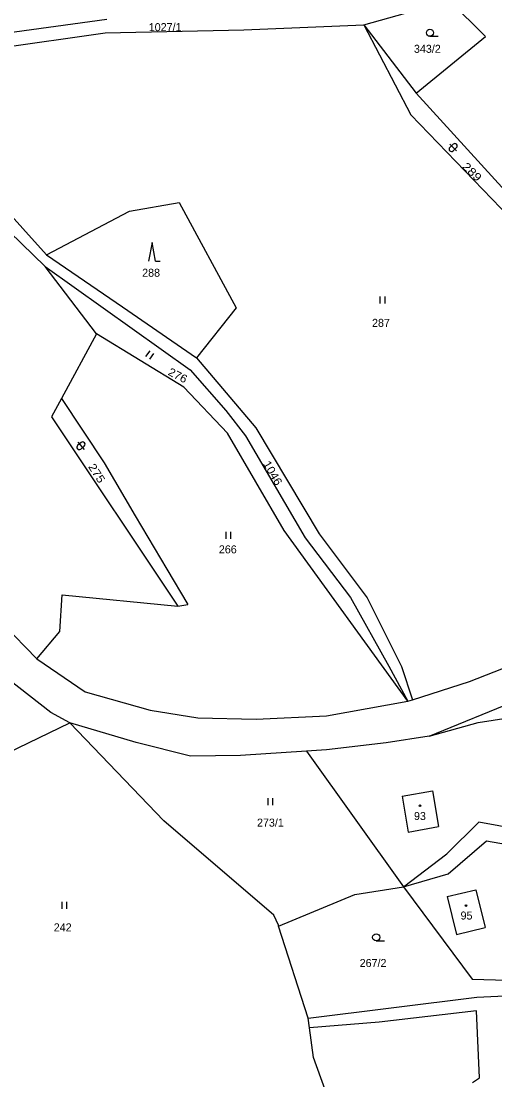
# Model space of a CAD drawing. Extents: x -744132 to -742433, y -984679 to -982287.
# Drawn here: x -743040.9 to -742940.3, y -984060.3 to -983835.5 of the extents above; entities that cross this region are included whole.
import ezdxf

# ---------------------------------------------------------------- set-up
doc = ezdxf.new("R2010")
doc.units = 0
doc.header["$LTSCALE"] = 0.68
for name, color, linetype, lineweight in [('1', 7, 'Continuous', 25), ('3', 7, 'Continuous', 25), ('5', 7, 'Continuous', 25)]:
    doc.layers.add(name, color=color, linetype=linetype, lineweight=lineweight)
doc.layers.add('2', color=7, linetype='Continuous')

msp = doc.modelspace()

# ---------------------------------------------------------------- linework, layer by layer
at = {"layer": '1'}
for p, q in [((-742968.16, -983836.35), (-742949.95, -983831.25)), ((-742949.95, -983831.25), (-742942.3, -983838.82)), ((-743022.73, -983835.22), (-743059.72, -983840.28)), ((-742993.61, -983837.37), (-742968.16, -983836.35)), ((-742968.16, -983836.35), (-742958.15, -983855.44)), ((-742968.16, -983836.35), (-742957.02, -983850.8)), ((-743061.62, -983843.55), (-743023.06, -983837.99)), ((-743023.06, -983837.99), (-742993.61, -983837.37)), ((-742957.02, -983850.8), (-742942.3, -983838.82)), ((-742957.02, -983850.8), (-742924.88, -983886.12)), ((-742958.15, -983855.44), (-742926.77, -983887.99)), ((-743045.62, -983873.99), (-743035.53, -983885.15)), ((-743017.93, -983875.92), (-743007.35, -983874.07)), ((-743007.35, -983874.07), (-742995.27, -983896.44)), ((-743047.81, -983876.13), (-743035.84, -983887.63)), ((-743035.53, -983885.15), (-743017.93, -983875.92)), ((-743035.53, -983885.15), (-743019.4, -983896.21)), ((-743035.84, -983887.63), (-743005.05, -983909.59)), ((-743024.89, -983901.91), (-743035.84, -983887.63)), ((-743019.4, -983896.21), (-743003.64, -983907.05)), ((-742995.27, -983896.44), (-743003.64, -983907.05)), ((-743024.89, -983901.91), (-743032.36, -983915.64)), ((-743006.34, -983913.24), (-743024.89, -983901.91)), ((-743003.64, -983907.05), (-742991.07, -983921.86)), ((-743005.05, -983909.59), (-742997.41, -983918.19)), ((-742997.12, -983923.03), (-743006.34, -983913.24)), ((-743032.36, -983915.64), (-743034.48, -983919.54)), ((-743032.36, -983915.64), (-743023.26, -983929.35)), ((-743034.48, -983919.54), (-743007.6, -983959.76)), ((-742997.41, -983918.19), (-742993.24, -983923.58)), ((-742991.07, -983921.86), (-742977.63, -983944.4)), ((-742985.08, -983943.71), (-742997.12, -983923.03)), ((-742993.24, -983923.58), (-742980.58, -983945.27)), ((-743023.26, -983929.35), (-743016.66, -983940.61)), ((-743016.66, -983940.61), (-743009.98, -983951.88)), ((-742958.81, -983979.95), (-742985.08, -983943.71)), ((-742980.58, -983945.27), (-742971, -983957.88)), ((-742977.63, -983944.4), (-742967.41, -983957.98)), ((-743009.98, -983951.88), (-743005.49, -983959.37)), ((-743032.69, -983965.11), (-743032.18, -983957.38)), ((-743032.18, -983957.38), (-743007.6, -983959.76)), ((-743007.6, -983959.76), (-743005.49, -983959.37)), ((-742971, -983957.88), (-742962.82, -983972.53)), ((-742967.41, -983957.98), (-742960.14, -983972.54)), ((-743044.73, -983963.56), (-743037.58, -983970.94)), ((-743037.58, -983970.94), (-743032.69, -983965.11)), ((-742945.7, -983975.78), (-742917.94, -983964.86)), ((-743037.58, -983970.94), (-743027.33, -983977.93)), ((-743034.59, -983982.35), (-743046.24, -983973.26)), ((-742962.82, -983972.53), (-742958.81, -983979.95)), ((-742960.14, -983972.54), (-742957.82, -983979.63)), ((-742957.82, -983979.63), (-742945.7, -983975.78)), ((-743027.33, -983977.93), (-743013.5, -983981.81)), ((-742954.25, -983987.39), (-742931.01, -983977.85)), ((-742976.07, -983983.01), (-742958.81, -983979.95)), ((-742958.81, -983979.95), (-742957.82, -983979.63)), ((-743030.59, -983984.53), (-743034.59, -983982.35)), ((-743013.5, -983981.81), (-743003.4, -983983.46)), ((-742943.85, -983984.44), (-742931.13, -983982.52)), ((-743053.26, -983995.45), (-743030.59, -983984.53)), ((-743010.64, -984005.31), (-743030.59, -983984.53)), ((-743003.4, -983983.46), (-742990.97, -983983.76)), ((-742990.97, -983983.76), (-742976.07, -983983.01)), ((-742954.25, -983987.39), (-742943.85, -983984.44)), ((-742994.34, -983991.43), (-743004.94, -983991.6)), ((-742980.31, -983990.54), (-742994.34, -983991.43)), ((-742976.04, -983990.27), (-742980.31, -983990.54)), ((-742980.31, -983990.54), (-742959.7, -984019.36)), ((-742959.98, -984000.08), (-742953.56, -983998.93)), ((-742959.98, -984000.08), (-742958.73, -984007.72)), ((-742953.56, -983998.93), (-742952.31, -984006.57)), ((-742987.25, -984025.33), (-743010.64, -984005.31)), ((-742958.73, -984007.72), (-742952.31, -984006.57)), ((-742950.5, -984012.36), (-742943.7, -984005.59)), ((-742922.34, -984009.55), (-742943.7, -984005.59)), ((-742950.23, -984016.58), (-742942.1, -984009.55)), ((-742942.1, -984009.55), (-742925.39, -984012.53)), ((-742959.7, -984019.36), (-742950.5, -984012.36)), ((-742959.7, -984019.36), (-742950.23, -984016.58)), ((-742970.06, -984020.95), (-742959.7, -984019.36)), ((-742959.7, -984019.36), (-742945.1, -984038.93)), ((-742950.46, -984021.4), (-742944.34, -984019.96)), ((-742944.34, -984019.96), (-742942.33, -984028)), ((-742986.22, -984027.72), (-742970.06, -984020.95)), ((-742950.46, -984021.4), (-742948.45, -984029.44)), ((-742986.28, -984027.52), (-742987.25, -984025.33)), ((-742986.22, -984027.72), (-742986.28, -984027.52)), ((-742979.99, -984047.22), (-742986.22, -984027.72)), ((-742948.45, -984029.44), (-742942.33, -984028)), ((-742945.1, -984038.93), (-742930.55, -984039.41)), ((-742979.99, -984047.22), (-742944.15, -984042.77)), ((-742944.15, -984042.77), (-742930.74, -984042.18)), ((-742979.7, -984049.29), (-742979.99, -984047.22)), ((-742944.22, -984045.71), (-742964.9, -984048.1)), ((-742964.9, -984048.1), (-742979.7, -984049.29)), ((-742978.8, -984055.59), (-742979.7, -984049.29)), ((-742976.37, -984062.42), (-742978.8, -984055.59))]:
    msp.add_line(p, q, dxfattribs=at)
for points in [[(-743004.94, -983991.6), (-743016.49, -983988.73), (-743030.59, -983984.53)], [(-742954.25, -983987.39), (-742963.39, -983988.8), (-742976.04, -983990.27)], [(-742945.05, -984060.92), (-742943.58, -984059.88), (-742944.22, -984045.71)]]:
    msp.add_lwpolyline(points, dxfattribs=at)
at = {"layer": '3'}
for p, q in [((-742954.093, -983838.76), (-742952.343, -983838.76)), ((-742949.149, -983861.668), (-742949.869, -983862.364)), ((-742949.857, -983861.656), (-742948.466, -983863.096)), ((-742949.174, -983863.084), (-742948.454, -983862.388)), ((-743012.37, -983886.52), (-743011.374, -983886.52)), ((-742964.631, -983895.48), (-742964.631, -983893.98)), ((-742963.63, -983895.48), (-742963.63, -983893.98)), ((-743014.423, -983906.74), (-743013.542, -983905.526)), ((-743013.613, -983907.328), (-743012.732, -983906.115)), ((-743028.143, -983924.993), (-743028.91, -983925.636)), ((-743028.848, -983924.931), (-743027.561, -983926.465)), ((-743028.267, -983926.403), (-743027.5, -983925.76)), ((-742997.391, -983945.49), (-742997.391, -983943.99)), ((-742996.39, -983945.49), (-742996.39, -983943.99)), ((-742988.451, -984002.02), (-742988.451, -984000.52)), ((-742987.45, -984002.02), (-742987.45, -984000.52)), ((-743032.211, -984024.01), (-743032.211, -984022.51)), ((-743031.21, -984024.01), (-743031.21, -984022.51)), ((-742965.513, -984030.82), (-742963.763, -984030.82))]:
    msp.add_line(p, q, dxfattribs=at)
msp.add_lwpolyline([(-743012.37, -983886.52), (-743013.12, -983882.52), (-743013.87, -983886.52)], dxfattribs=at)
for centre in [(-742954.0929, -983838.0098), (-742965.5129, -984030.0698)]:
    msp.add_circle(centre, 0.75, dxfattribs=at)
for centre, start, end in [((-742949.521, -983862.7233), 134, 313.98788), ((-742948.8016, -983862.0286), 314, 134), ((-743028.5877, -983926.0192), 130, 309.98789), ((-743027.8216, -983925.3764), 310, 130)]:
    msp.add_arc(centre, 0.5, start, end, dxfattribs=at)
at = {"layer": '5'}
for centre in [(-742956.2168, -984002.1392), (-742946.4468, -984023.3192)]:
    msp.add_circle(centre, 0.175, dxfattribs=at)

# ---------------------------------------------------------------- texts
at = {"layer": '2'}
for s, p in [('1027/1', (-743013.81, -983837.665)), ('343/2', (-742957.49, -983842.265)), ('288', (-743015.21, -983889.815)), ('287', (-742966.39, -983900.455)), ('266', (-742998.92, -983948.545)), ('273/1', (-742990.82, -984006.565)), ('93', (-742957.48, -984005.165)), ('95', (-742947.59, -984026.295)), ('242', (-743033.98, -984028.805)), ('267/2', (-742969.02, -984036.375))]:
    msp.add_text(s, height=1.7, dxfattribs=at).set_placement(p)
for s, rotation, width, p in [('289', 316, 1.2, (-742947.375, -983866.565)), ('276', 333, 1.1, (-743009.882, -983910.568)), ('275', 303, 1.15, (-743026.756, -983930.151)), ('1046', 300, 1.1, (-742989.598, -983929.502))]:
    msp.add_text(s, height=1.7, rotation=rotation, dxfattribs=dict(at, width=width)).set_placement(p)

doc.saveas('drawing.dxf')
